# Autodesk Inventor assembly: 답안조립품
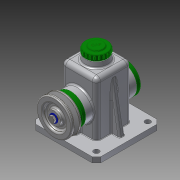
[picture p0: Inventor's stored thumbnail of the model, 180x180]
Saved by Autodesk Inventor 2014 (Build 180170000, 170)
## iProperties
Created: 2017-08
Part Number: 답안조립품
Document SubType Name: Assembly
Designer: user
Author: user
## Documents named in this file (14)
- E:\470825V1009\답안조립품.iam
- E:\470825V1009\본체.ipt
- E:\470825V1009\베어링 15 x 35 x 11.ipt
- E:\470825V1009\뒤커버.ipt
- E:\470825V1009\앞커버.ipt
- E:\470825V1009\오일실 15 25 7.ipt
- E:\470825V1009\축.ipt
- E:\470825V1009\멈춤링 15 x 1.ipt
- E:\470825V1009\키 5 x 5 x 14.ipt
- E:\470825V1009\V-벨트풀리.ipt
- E:\470825V1009\볼트 M6 x 12.ipt
- E:\470825V1009\와셔.ipt
- E:\470825V1009\볼트 M4 x 10.ipt
- E:\470825V1009\상부캡.ipt
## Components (1 placed, 1 different names)
1. V-벨트풀리:1 — 각도:2
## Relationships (1: Angle 1)
- 각도:2 [Angle]: V-벨트풀리:1
